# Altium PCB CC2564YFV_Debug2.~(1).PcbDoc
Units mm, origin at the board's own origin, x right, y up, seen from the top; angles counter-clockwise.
Board outline 229.87 x 45.72 mm, 2 copper layers (Top Layer, Bottom Layer); 77 components, 123 nets, 422 pads, 88 vias.
Unrouted connection lines stored in the file: 7.
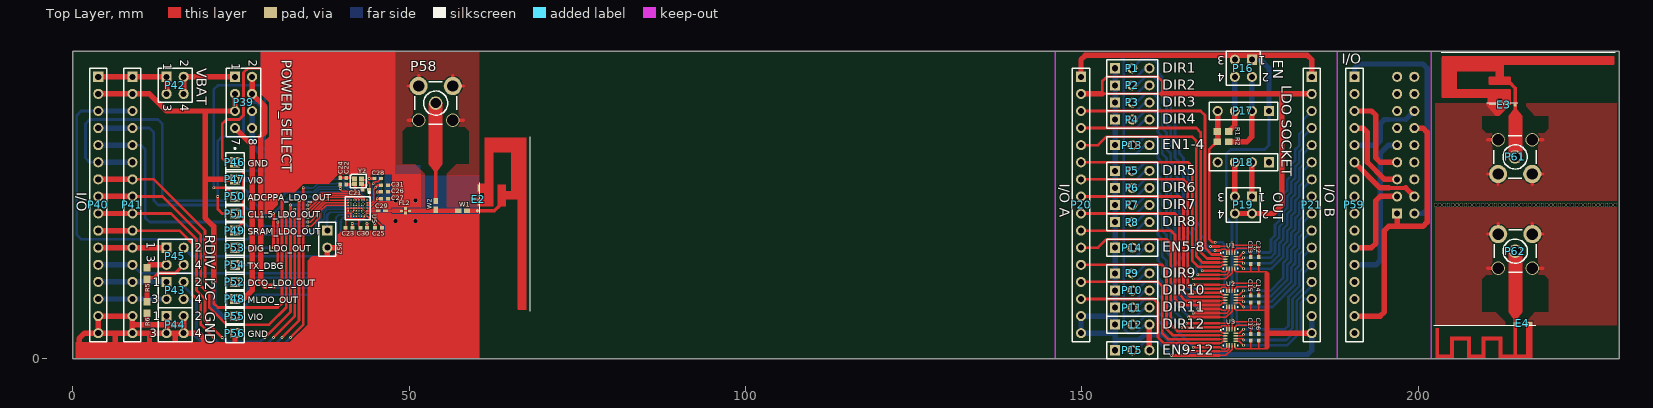
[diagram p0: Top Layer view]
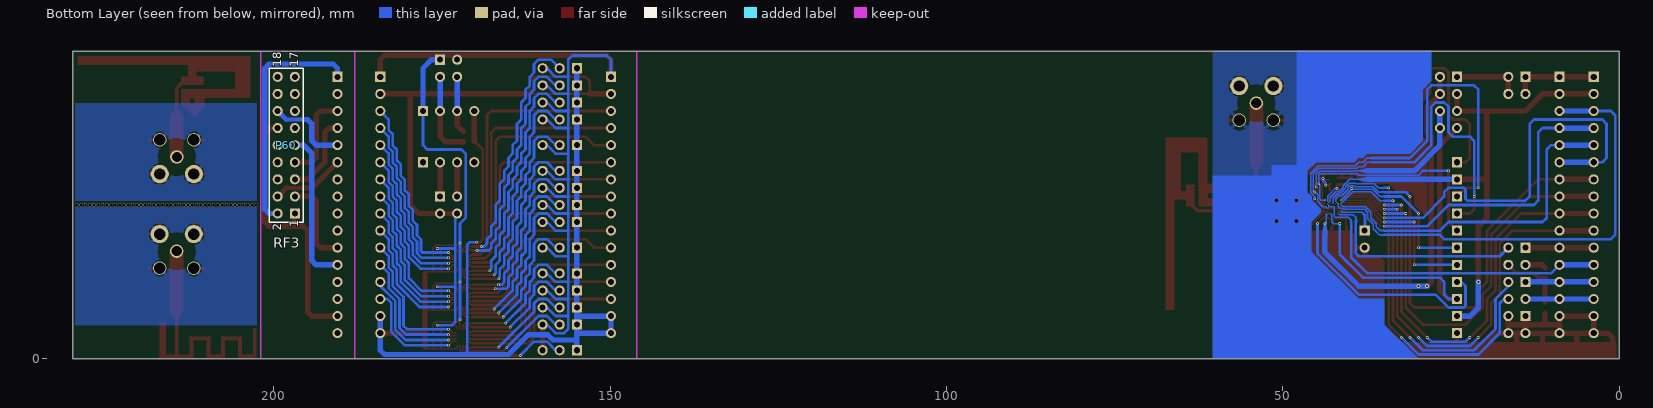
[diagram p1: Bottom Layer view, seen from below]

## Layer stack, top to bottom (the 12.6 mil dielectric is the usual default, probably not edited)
Top Solder: solder mask 0.0102, Solder Resist, Dk 3.5
Top Layer: signal copper 0.0356
Dielectric 1: dielectric 0.32, FR-4, Dk 4.8
Bottom Layer: signal copper 0.0356
Bottom Solder: solder mask 0.0102, Solder Resist, Dk 3.5

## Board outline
0,0 229.87,0 229.87,45.72 0,45.72

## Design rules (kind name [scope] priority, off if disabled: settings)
Clearance [All] p1: gap=0.1
ComponentClearance [All] p1 off: gap=0.1 collisioncheckmode=3 verticalgap=0.1 showdistances=FALSE
HoleSize [All] p1: absolutevalues=TRUE maxlimit=2.54 minlimit=0.1 maxpercent=80.000 minpercent=20.000
HoleToHoleClearance [All] p1: gap=0.1 allowstackedmicrovias=TRUE
MinimumSolderMaskSliver [All] p1: minsoldermaskwidth=0.1
PolygonConnect [All] p1: connectstyle=Relief reliefconductorwidth=0.5 reliefentries=4 polygonreliefangle="45 Angle" airgapwidth=0.2
RoutingVias [All] p1: holewidth=0.2 width=0.25 viastyle="Through Hole" minholewidth=0.1 minwidth=0.25 maxholewidth=0.2 maxwidth=0.45
SilkToSilkClearance [All] p1: silktosilkclearance=0.1
SilkToSolderMaskClearance [IsPad] p1 off: minsilkscreentomaskgap=0.1 clearancetoexposedcopper=TRUE
SolderMaskExpansion [All] p1: expansion=0.102
Width [All] p1: maxlimit=6 minlimit=0.1 preferedwidth=0.2
23 further rules are at their usual default settings.

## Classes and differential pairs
component class CC2564YFV_Debug_Add: E3 E4 P59 P60 P61 P62
component class CC2564YFV_Debug_Power: C12 C13 C14 C15 C16 C17 P1 P2 P3 P4 P5 P6 P7 P8 P9 P10 P11 P12 P13 P14 P15 P16 P17 P18 P19 P20 P21 R1 R2 U1 U2 U3
component class CC2564YFV_Debug_RF2: C21 C22 C23 C24 C25 C26 C27 C28 C29 C30 C31 E2 FL2 P39 P40 P41 P42 P43 P44 P45 P46 P47 P48 P49 P50 P51 P52 P53 P54 P55 P56 P57 P58 R5 R6 U5 W1 W2 Y2

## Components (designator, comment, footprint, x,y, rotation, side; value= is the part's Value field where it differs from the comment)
C12 "CC0402KRX7R8BB104" 0402 176.3,14.6 r270 top
C13 "CC0402KRX7R8BB104" 0402 175.1,14.6 r90 top
C14 "CC0402KRX7R8BB104" 0402 176.3,8.9 r270 top
C15 "CC0402KRX7R8BB104" 0402 175.1,8.9 r90 top
C16 "CC0402KRX7R8BB104" 0402 176.3,3.2 r270 top
C17 "CC0402KRX7R8BB104" 0402 175.1,3.2 r90 top
C21 "Cap Semi 8 pF" 0402 43.56,25.1 r0 top
C22 "Cap Semi 8 pF" 0402 40.66,26.4 r270 top
C23 "C1005X5R1A105K050BB" 0402 41.06,19.5 r0 top
C24 "C1005X7R1H104M050BB" 0402 39.76,26.4 r270 top
C25 "C1005X7R1H104M050BB" 0402 45.46,19.5 r180 top
C26 "C1005X7R1H104M050BB" 0402 46.36,24.8 r180 top
C27 "C1005X7R1H104M050BB" 0402 46.36,23.8 r180 top
C28 "C1005X7R1H104M050BB" 0402 45.36,26.8 r0 top
C29 "GRM0335C1E220JA01D" 1-0201 45.96,22 r0 top
C30 "C1005X7R1H104M050BB" 0402 43.26,19.5 r0 top
C31 "C1005X5R1A105K050BB" 0402 46.36,25.8 r180 top
E2 "Inverted F Antenna" Inverted_F_Antenna 60.16,22 r270 top
E3 "Inverted F Antenna" Inverted_F_Antenna 214.38,37.7 r0 top
E4 "Meandered IFA" Meandered_IFA 216.95,5 r180 top
FL2 "FI105L250014" FL105_Electrodes 49.46,22 r0 top
P1 "DIR1" HDR1X3 154.94,43.18 r0 top
P2 "DIR2" HDR1X3 154.94,40.64 r0 top
P3 "DIR3" HDR1X3 154.94,38.1 r0 top
P4 "DIR4" HDR1X3 154.94,35.56 r0 top
P5 "DIR5" HDR1X3 154.94,27.94 r0 top
P6 "DIR6" HDR1X3 154.94,25.4 r0 top
P7 "DIR7" HDR1X3 154.94,22.86 r0 top
P8 "DIR8" HDR1X3 154.94,20.32 r0 top
P9 "DIR9" HDR1X3 154.94,12.7 r0 top
P10 "DIR10" HDR1X3 154.94,10.16 r0 top
P11 "DIR11" HDR1X3 154.94,7.62 r0 top
P12 "DIR12" HDR1X3 154.94,5.08 r0 top
P13 "EN1-4" HDR1X3 154.94,31.75 r0 top
P14 "EN5-8" HDR1X3 154.94,16.51 r0 top
P15 "EN9-12" HDR1X3 154.94,1.27 r0 top
P16 "EN" HDR2X2 175.26,44.45 r180 top
P17 "LDO SOCKET" HDR1X4 177.8,36.83 r180 top
P18 "LDO SOCKET" HDR1X4 177.8,29.21 r180 top
P19 "OUT" HDR2X2 175.26,24.13 r180 top
P20 "I/O A" HDR1X16 149.86,41.91 r270 top
P21 "I/O B" HDR1X16 184.15,41.91 r270 top
P39 "POWER_SELECT" HDR2X4 24.13,41.91 r270 top
P40 "I/O" HDR1X16 3.81,41.91 r270 top
P41 "I/O" HDR1X16 8.89,41.91 r270 top
P42 "VBAT" HDR2X2 13.97,41.91 r270 top
P43 "I2C" HDR2X2 13.97,11.43 r270 top
P44 "GND" HDR2X2 13.97,6.35 r270 top
P45 "RDIV" HDR2X2 13.97,16.51 r270 top
P46 "GND" PIN1 24.13,29.21 r0 top
P47 "VIO" PIN1 24.13,26.67 r0 top
P48 "MLDO_OUT" PIN1 24.13,8.89 r0 top
P49 "SRAM_LDO_OUT" PIN1 24.13,19.05 r0 top
P50 "ADCPPA_LDO_OUT" PIN1 24.13,24.13 r0 top
P51 "CL1.5_LDO_OUT" PIN1 24.13,21.59 r0 top
P52 "DCO_LDO_OUT" PIN1 24.13,11.43 r0 top
P53 "DIG_LDO_OUT" PIN1 24.13,16.51 r0 top
P54 "TX_DBG" PIN1 24.13,13.97 r0 top
P55 "VIO" PIN1 24.13,6.35 r0 top
P56 "GND" PIN1 24.13,3.81 r0 top
P57 "G5" HDR1X2 37.846,19.05 r270 top
P58 "SMA" SMA#1 53.96,38 r0 top
P59 "I/O" HDR1X16 190.5,41.91 r270 top
P60 "RF3" HDR2X9 196.85,21.59 r90 bottom
P61 "SMA" SMA#2 214.38,30 r0 top
P62 "SMA" SMA#1 214.4,16 r0 top
R1 "Res Chip 10 K" 3-0603 170.942,33.782 r0 top
R2 "Res Chip 10 K" 3-0603 170.942,32.258 r0 top
R5 "Res Chip 10 K" 3-0603 11.049,12.7 r90 top
R6 "Res Chip 12 K" 3-0603 11.049,7.62 r90 top
U1 "SN74AVC4T774RSV" RSV16 172.1,14.6 r0 top
U2 "SN74AVC4T774RSV" RSV16 172.1,8.9 r0 top
U3 "SN74AVC4T774RSV" RSV16 172.1,3.2 r0 top
U5 "CC2564YFV" "YFV (R-XBGA-N54)" 42.36,22.2 r270 top
W1 "Chip Jumper Short" 2-0402 57.96,22 r180 top
W2 "Chip Jumper Open" 2-0402 53.96,22.8 r90 top
Y2 "NX1612AA-26MHZ-TI2" XTAL_QUAD_1.6x1.2mm 42.435,26.375 r180 top

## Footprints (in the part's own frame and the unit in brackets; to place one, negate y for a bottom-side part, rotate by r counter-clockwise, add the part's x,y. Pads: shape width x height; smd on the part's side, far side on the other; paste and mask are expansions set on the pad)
1-0201 [mm] "Chip Resistor; Body 0.6 x 0.3 mm (LxW typ)"
  rect 0.7x0.4 smd: 1(-0.525,0) 2(0.525,0)
2-0402 [mm] "Chip Resistor; Body 1 x 0.5 mm (LxW typ)"
  rect 0.9x0.7 smd: 1(-0.65,0) 2(0.65,0)
3-0603 [mm] "Chip Resistor; Body 1.6 x 0.9 mm (LxW typ)"
  rect 1.1x1 smd: 1(-0.85,0) 2(0.85,0)
0402 [mm] "Chip Capacitor, Body 1.0x0.5mm, IPC High Density"
  rect 0.6x0.5 smd: 1(-0.5,0) 2(0.5,0)
  body extent -0.55,-0.3 0.55,0.3, height 1.3
FL105_Electrodes [mm]
  round 0.6 hole 0.6: 1(-1.5,1.5) 1(1.5,1.5) 3(-1.5,-1.5) 3(1.5,-1.5)
  rect 0.4x0.45 smd: 1(0,0.35) 3(0,-0.35)
  rect 0.45x0.3 smd: 2(0.575,0) 4(-0.575,0)
  Top Layer region: -2,0.5 2,0.5 2,2 -2,2
  Top Layer region: -2,-2 2,-2 2,-0.5 -2,-0.5
  Top Layer region: -2,-0.3 -0.5,-0.3 -0.5,0.3 -2,0.3
  Top Layer region: 0.5,-0.3 2,-0.3 2,0.3 0.5,0.3
  Top Layer region: -0.2,-0.5 0.2,-0.5 0.2,0.5 -0.2,0.5
  Top Layer region: 0.425,-0.15 0.5,-0.3 0.5,-0.15
  Top Layer region: -0.425,-0.15 -0.5,-0.3 -0.5,-0.15
  Top Layer region: 0.425,0.15 0.5,0.3 0.5,0.15
  Top Layer region: -0.5,0.3 -0.425,0.15 -0.5,0.15
HDR1X2 [mm] "Connector; Header; 2 Position"
  rect 1.5x1.5 hole 0.9: 1(0,0)
  round 1.5 hole 0.9: 2(2.54,0)
  silkscreen extent -1.27,-1.27 3.81,1.27
HDR1X3 [mm] "Connector; Header; 3 Position"
  rect 1.5x1.5 hole 0.9: 1(0,0)
  round 1.5 hole 0.9: 2(2.54,0) 3(5.08,0)
  silkscreen extent -1.27,-1.27 6.35,1.27
HDR1X4 [mm] "Connector; Header; 4 Position"
  rect 1.5x1.5 hole 0.9: 1(0,0)
  round 1.5 hole 0.9: 2(2.54,0) 3(5.08,0) 4(7.62,0)
  silkscreen extent -1.27,-1.27 8.89,1.27
HDR1X16 [mm] "Connector; Header; 16 Position"
  rect 1.5x1.5 hole 0.9: 1(0,0)
  round 1.5 hole 0.9: 2(2.54,0) 3(5.08,0) 4(7.62,0) 5(10.16,0) 6(12.7,0) 7(15.24,0) 8(17.78,0) 9(20.32,0) 10(22.86,0) 11(25.4,0) 12(27.94,0) 13(30.48,0) 14(33.02,0) 15(35.56,0) 16(38.1,0)
  silkscreen extent -1.27,-1.27 39.37,1.27
HDR2X2 [mm] "Connector; Header; 2x2 Position"
  rect 1.5x1.5 hole 0.9: 1(0,0)
  round 1.5 hole 0.9: 2(0,2.54) 3(2.54,0) 4(2.54,2.54)
  silkscreen extent -1.27,-1.27 3.81,3.81
HDR2X4 [mm] "Connector; Header; 4x2 Position"
  rect 1.5x1.5 hole 0.9: 1(0,0)
  round 1.5 hole 0.9: 2(0,2.54) 3(2.54,0) 4(2.54,2.54) 5(5.08,0) 6(5.08,2.54) 7(7.62,0) 8(7.62,2.54)
  silkscreen extent -1.27,-1.27 8.89,3.81
HDR2X9 [mm] "Connector; Header; 9x2 Position"
  rect 1.5x1.5 hole 0.9: 1(0,0)
  round 1.5 hole 0.9: 2(0,2.54) 3(2.54,0) 4(2.54,2.54) 5(5.08,0) 6(5.08,2.54) 7(7.62,0) 8(7.62,2.54) 9(10.16,0) 10(10.16,2.54) 11(12.7,0) 12(12.7,2.54) 13(15.24,0) 14(15.24,2.54) 15(17.78,0) 16(17.78,2.54) 17(20.32,0) 18(20.32,2.54)
  silkscreen extent -1.27,-1.27 21.59,3.81
Inverted_F_Antenna [mm]
  round 0.46 smd mask+0: 1(0,0)
  rect 1x0.3 smd paste+0 mask+0: 2(-1.272,0.165) 3(-3.367,0.183)
  Top Layer region: -10.77,1.092 -10.237,1.092 -4.039,1.067 -4.039,0.127 -4.032,0.088 -4.009,0.055 -3.976,0.033 -3.937,0.025 -3.937,0.025 -2.788,0.025 -2.749,0.033 -2.716,0.055 -2.694,0.088 -2.686,0.127 -2.686,0.127 -2.686,1.025 -1.89,1.025 -1.89,0.127 -1.882,0.088 -1.86,0.055 -1.827,0.033 -1.788,0.025 -1.788,0.025 -0.788,0.025 -0.767,0.027 -0.747,0.033 -0.747,0.033 -0.702,0.051 -0.669,0.087 -0.658,0.135 -0.658,0.135 -0.658,0.135 -0.658,0.135 -0.658,0.135 -0.66,2.23 -0.67,2.274 -0.698,2.309 -0.698,2.309 -0.698,2.309 -0.721,2.338 -0.752,2.356 -0.788,2.363 -0.788,2.363 -8.686,2.363 -8.686,5.025 -2.89,5.025 -2.89,4.229 -3.788,4.229 -3.827,4.221 -3.86,4.199 -3.882,4.166 -3.89,4.127 -3.89,4.127 -3.89,3.127 -3.882,3.088 -3.86,3.055 -3.827,3.033 -3.788,3.025 -3.788,3.025 -0.83,3.025 -0.231,2.426 -0.231,0 -0.208,-0.1 -0.144,-0.18 -0.052,-0.225 0.051,-0.225 0.143,-0.18 0.207,-0.1 0.23,0 0.23,0 0.23,2.521 0.212,2.61 0.162,2.685 0.162,2.685 -0.686,3.533 -0.686,4.127 -0.694,4.166 -0.716,4.199 -0.749,4.221 -0.788,4.229 -0.788,4.229 -1.686,4.229 -1.686,6.025 14.63,6.025 14.669,6.033 14.702,6.055 14.724,6.088 14.732,6.127 14.732,6.127 14.732,7.137 14.724,7.176 14.702,7.21 14.669,7.232 14.63,7.239 14.63,7.239 -10.77,7.239 -10.809,7.232 -10.842,7.21 -10.864,7.176 -10.872,7.137 -10.872,7.137 -10.872,1.194 -10.864,1.155 -10.842,1.122 -10.809,1.1 -10.77,1.092
  silkscreen extent -11,0.34 14.9,7.86
Meandered_IFA [mm] "Meandered Inverted F Antenna"
  rect 0.5x0.5 smd mask+0: 1(2.55,-0.25)
  rect 0.9x0.5 smd mask+0: 2(0.45,-0.25)
  Top Layer region: 0,-0.5 0,4.89 5,4.89 5,2.25 7,2.25 7,4.89 9.7,4.89 9.7,2.25 11.7,2.25 11.7,4.89 14.4,4.89 14.4,0.45 13.9,0.45 13.9,4.39 12.2,4.39 12.2,1.75 9.2,1.75 9.2,4.39 7.5,4.39 7.5,1.75 4.5,1.75 4.5,4.39 2.8,4.39 2.8,-0.5 2.3,-0.5 2.3,4.39 0.9,4.39 0.9,-0.5
  silkscreen extent -0.5,0 14.7,0
PIN1 [mm] "Connector; Plug"
  rect 1.5x1.5 hole 0.9: 1(0,0)
  silkscreen extent -1.4,-1.4 1.4,2.17
RSV16 [mm] "QFN, 16-Leads, Body 1.8x2.6mm, Pitch 0.4mm, TI Recommended"
  rect 0.75x0.2 smd paste-0.1 mask+0.05: 1(-0.725,0.6)
  rect 0.65x0.2 smd paste-0.1 mask+0.05: 2(-0.775,0.2) 3(-0.775,-0.2) 4(-0.775,-0.6) 9(0.775,-0.6) 10(0.775,-0.2) 11(0.775,0.2) 12(0.775,0.6)
  rect 0.2x0.65 smd paste-0.1 mask+0.05: 5(-0.6,-1.175) 6(-0.2,-1.175) 7(0.2,-1.175) 8(0.6,-1.175) 13(0.6,1.175) 14(0.2,1.175) 15(-0.2,1.175) 16(-0.6,1.175)
  silkscreen extent -1.52,-1.33 1.08,1.33, body extent -0.92,-1.32 0.92,1.33, height 0.55
SMA#1 [mm] "Connector; SMA Generic"
  round 2 hole 1.5: 1(0,0)
  round 2 hole 1.7: 2(-2.54,-2.54) 2(2.54,-2.54)
  round 2.7 hole 1.7: 2(-2.54,2.54) 2(2.54,2.54)
  silkscreen extent -3.15,-3.15 3.15,3.15
SMA#2 [mm] "Connector; SMA Generic"
  round 2 hole 1.5: 1(0,0)
  round 2.7 hole 1.7: 2(-2.54,-2.54) 2(2.54,-2.54)
  round 2 hole 1.7: 2(-2.54,2.54) 2(2.54,2.54)
  silkscreen extent -3.15,-3.15 3.15,3.15
XTAL_QUAD_1.6x1.2mm [mm]
  rect 0.75x0.65 smd: 1(-0.525,-0.375) 2(0.525,-0.375) 3(0.525,0.375) 4(-0.525,0.375)
  silkscreen extent -1.2,-1.02 1.2,0.98
"YFV (R-XBGA-N54)" [mm] "BGA, 54-Balls, Pitch 0.4mm"
  round 0.2 smd: A1(-1.4,1.4) A2(-1,1.4) A3(-0.6,1.4) A4(-0.2,1.4) A5(0.2,1.4) A6(0.6,1.4) A7(1,1.4) B1(-1.4,1) B2(-1,1) B3(-0.6,1) B4(-0.2,1) B6(0.6,1) B7(1,1) C1(-1.4,0.6) C2(-1,0.6) C3(-0.6,0.6) C4(-0.2,0.6) C5(0.2,0.6) C6(0.6,0.6) C7(1,0.6) D1(-1.4,0.2) D2(-1,0.2) D3(-0.6,0.2) D4(-0.2,0.2) D5(0.2,0.2) D6(0.6,0.2) D7(1,0.2) E1(-1.4,-0.2) E2(-1,-0.2) E3(-0.6,-0.2) E4(-0.2,-0.2) E5(0.2,-0.2) E6(0.6,-0.2) E7(1,-0.2) F1(-1.4,-0.6) F2(-1,-0.6) F3(-0.6,-0.6) F4(-0.2,-0.6) F5(0.2,-0.6) F6(0.6,-0.6) F7(1,-0.6) G1(-1.4,-1) G2(-1,-1) G3(-0.6,-1) G4(-0.2,-1) G5(0.2,-1) G6(0.6,-1) G7(1,-1) H1(-1.4,-1.4) H2(-1,-1.4) H3(-0.6,-1.4) H4(-0.2,-1.4) H5(0.2,-1.4) H7(1,-1.4)
  silkscreen extent -2.65,-1.88 1.52,1.88, body extent -1.91,-1.91 1.52,1.91, height 0.5

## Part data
C12 C13 C14 C15 C16 C17: "0.1 uF/25 V 0402"
C21 C22: "Chip Capacitor, 8 pF"
C23 C31: "1.0 uF/10 V 0402"
C24 C25 C26 C27 C28 C30: "0.1 uF/50 V 0402"
C29: "22 pF/25 V 0201"
E2 E3: "Inverted F Antenna (Design Note DN0007; SWRU120B)"
E4: "Meandered Inverted F Antenna (Application Note AN043; SWRA117D)"
FL2: "2.4 GHz Low Pass Filter"
P1 P2 P3 P4 P5 P6 P7 P8 P9 P10 P11 P12 P13 P14 P15: library part "Header 3", "Header, 3-Pin"
P16 P19 P42 P43 P44 P45: library part "Header 2X2", "Header, 2-Pin, Dual row"
P17 P18: library part "Header 4", "Header, 4-Pin"
P20 P21 P40 P41 P59: library part "Header 16", "Header, 16-Pin"
P39: library part "Header 4X2", "Header, 4-Pin, Dual row"
P46 P47 P48 P49 P50 P51 P52 P53 P54 P55 P56: library part Plug, "Plug"
P57: library part "Header 2", "Header, 2-Pin"
P58 P61 P62: "SMA Generic Connector"
P60: library part "Header 9X2", "Header, 9-Pin, Dual row"
R1 R2 R5: "Chip Resistor, 10 K"
R6: "Chip Resistor, 12 K"
U1 U2 U3: "4-Bit Dual-Supply Bus Transceiver With Configurable Voltage Translation and 3-State Outputs"
U5: "CC2564, 54-balls DSBGA"
Y2: "Crystal Oscillator 26 MHz"

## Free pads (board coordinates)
  round 0.5 hole 0.5 paste+0 mask+0: 0(202.565,22.86) 0(203.2,22.86) 0(203.835,22.86) 0(204.47,22.86) 0(205.105,22.86) 0(205.74,22.86) 0(206.375,22.86) 0(207.01,22.86) 0(207.645,22.86) 0(208.28,22.86) 0(208.915,22.86) 0(209.55,22.86) 0(210.185,22.86) 0(210.82,22.86) 0(211.455,22.86) 0(212.09,22.86) 0(212.725,22.86) 0(213.36,22.86) 0(213.995,22.86) 0(214.63,22.86) 0(215.265,22.86) 0(215.9,22.86) 0(216.535,22.86) 0(217.17,22.86) 0(217.805,22.86) 0(218.44,22.86) 0(219.075,22.86) 0(219.71,22.86) 0(220.345,22.86) 0(220.98,22.86) 0(221.615,22.86) 0(222.25,22.86) 0(222.885,22.86) 0(223.52,22.86) 0(224.155,22.86) 0(224.79,22.86) 0(225.425,22.86) 0(226.06,22.86) 0(226.695,22.86) 0(227.33,22.86) 0(227.965,22.86) 0(228.6,22.86) 0(229.235,22.86)

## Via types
v1: diameter 0.4, hole 0.2, Top Layer to Bottom Layer, 70 vias
v2: diameter 0.25, hole 0.1, Top Layer to Bottom Layer, 15 vias
v3: diameter 0.6, hole 0.3, Top Layer to Bottom Layer, 3 vias

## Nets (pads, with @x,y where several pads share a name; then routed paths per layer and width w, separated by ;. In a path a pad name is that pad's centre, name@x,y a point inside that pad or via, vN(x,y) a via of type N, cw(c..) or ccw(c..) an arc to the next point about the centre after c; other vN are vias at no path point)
A1: P20.3 U1.1 | length 42
  Top Layer w0.2: 170.4,15.5 170.6,15.5 170.9,15.2 U1.1
  Top Layer w0.4: P20.3 167.64,36.83 168.275,36.195 168.275,16.51 169.285,15.5 170.4,15.5
A2: P20.4 U1.2 | length 40
  Top Layer w0.2: 170.4,14.9 170.8,14.9 170.9,14.8 U1.2
  Top Layer w0.4: P20.4 167.005,34.29 167.64,33.655 167.64,15.875 168.615,14.9 170.4,14.9
A3: P20.5 U1.3 | length 39.8
  Top Layer w0.2: 170.4,14.3 170.8,14.3 170.9,14.4 U1.3
  Top Layer w0.4: P20.5 152.4,31.75 153.67,33.02 166.37,33.02 167.005,32.385 167.005,15.24 167.945,14.3 170.4,14.3
A4: P20.6 U1.4 | length 36.2
  Top Layer w0.2: 170.4,13.7 170.6,13.7 170.9,14 U1.4
  Top Layer w0.4: P20.6 165.735,29.21 166.37,28.575 166.37,14.605 167.275,13.7 170.4,13.7
A5: P20.7 U2.1 | length 37.6
  Top Layer w0.2: 170.4,9.8 170.6,9.8 170.9,9.5 U2.1
  Top Layer w0.4: P20.7 165.1,26.67 165.735,26.035 165.735,10.795 166.73,9.8 170.4,9.8
A6: P20.8 U2.2 | length 35.5
  Top Layer w0.2: 170.4,9.2 170.8,9.2 170.9,9.1 U2.2
  Top Layer w0.4: P20.8 164.465,24.13 165.1,23.495 165.1,10.16 166.06,9.2 170.4,9.2
A7: P20.9 U2.3 | length 33.6
  Top Layer w0.2: 170.4,8.6 170.8,8.6 170.9,8.7 U2.3
  Top Layer w0.4: P20.9 163.83,21.59 164.465,20.955 164.465,9.525 165.39,8.6 170.4,8.6
A8: P20.10 U2.4 | length 31.7
  Top Layer w0.2: 170.4,8 170.6,8 170.9,8.3 U2.4
  Top Layer w0.4: P20.10 163.195,19.05 163.83,18.415 163.83,8.89 164.72,8 170.4,8
A9: P20.11 U3.1 | length 34.9
  Top Layer w0.2: 170.4,4.1 170.6,4.1 170.9,3.8 U3.1
  Top Layer w0.4: P20.11 152.4,16.51 153.67,17.78 162.56,17.78 163.195,17.145 163.195,5.08 164.175,4.1 170.4,4.1
A10: P20.12 U3.2 | length 31.1
  Top Layer w0.2: 170.4,3.5 170.8,3.5 170.9,3.4 U3.2
  Top Layer w0.4: P20.12 161.925,13.97 162.56,13.335 162.56,4.445 163.505,3.5 170.4,3.5
A11: P20.13 U3.3 | length 29.1
  Top Layer w0.2: 170.4,2.9 170.8,2.9 170.9,3 U3.3
  Top Layer w0.4: P20.13 161.29,11.43 161.925,10.795 161.925,3.81 162.835,2.9 170.4,2.9
A12: P20.14 U3.4 | length 27.3
  Top Layer w0.2: 170.4,2.3 170.6,2.3 170.9,2.6 U3.4
  Top Layer w0.4: P20.14 160.655,8.89 161.29,8.255 161.29,3.175 162.165,2.3 170.4,2.3
ADCPPA_LDO_OUT_1: 
ADCPPA_LDO_OUT_2: C27.2 P50.1 U5.A4 | length 60
  Top Layer w0.2: U5.A4 44.06,22.4 v1@45.26,23.6
  Top Layer w0.4: v1(20.955,25.4) 22.86,25.4 P50.1 ; v1(45.26,23.8) C27.2
  Bottom Layer w0.2: 36.83,29.845 37.465,29.845 38.1,29.21 38.735,29.21 39.245,28.7 44.76,28.7 45.86,27.6 45.86,24.7 45.26,24.1 v1(45.26,23.8)
  Bottom Layer w0.4: v1(20.955,25.4) 20.955,40.005 21.59,40.64 27.94,40.64 28.575,40.005 28.575,32.385 31.115,29.845 36.83,29.845
ANTENNA: FL2.2 W1.2 W2.1 | length 6.8
  Top Layer w0.6: 50.46,22 W1.2
AUD_CLK_2: P40.8 P41.8 U5.E1 | length 68
  Top Layer w0.2: v1(34.925,21.59) 34.95,21.59 37.36,24 41.784,24 42.16,23.624 U5.E1
  Top Layer w0.4: P41.8 13.335,24.13 19.05,18.415 19.05,10.795 20.32,9.525 20.32,7.62 22.86,5.08 29.21,5.08 31.75,7.62 v1(31.75,21.59)
  Top Layer w0.8: P40.8 P41.8
  Bottom Layer w0.4: v1(31.75,21.59) v1(34.925,21.59)
AUD_FSYNC_2: P40.7 P41.7 U5.E2 | length 70.2
  Top Layer w0.4: P41.7 12.065,26.67 19.685,19.05 19.685,11.43 20.955,10.16 20.955,8.255 21.59,7.62 30.48,7.62 31.115,8.255 v1(31.115,24.13)
  Top Layer w0.8: P40.7 P41.7
  Bottom Layer w0.2: 34.925,24.765 35.725,24.765 36.56,25.6 39.36,25.6 39.46,25.7 40.06,25.7 40.26,25.5 40.26,25.2 41.26,24.2 41.76,24.2 42.16,23.8 v2(42.16,23.2)
  Bottom Layer w0.4: v1(31.115,24.13) 31.75,24.765 34.925,24.765
AUD_IN_2: P40.9 P41.9 U5.C1 | length 72.3
  Top Layer w0.2: v1(34.925,22.86) 35.22,22.86 36.96,24.6 42.136,24.6 42.96,23.776 U5.C1
  Top Layer w0.4: P41.9 14.605,21.59 18.415,17.78 18.415,10.16 19.685,8.89 19.685,5.715 v1(22.225,3.175) ; v1(28.575,3.175) 32.385,6.985 v1(32.385,22.86)
  Top Layer w0.8: P40.9 P41.9
  Bottom Layer w0.4: v1(22.225,3.175) 22.86,2.54 27.94,2.54 v1(28.575,3.175) ; v1(32.385,22.86) v1(34.925,22.86)
AUD_OUT_2: P40.10 P41.10 U5.D1 | length 71.1
  Top Layer w0.2: v1(34.925,22.225) 35.085,22.225 37.16,24.3 41.96,24.3 42.56,23.7 U5.D1
  Top Layer w0.4: P41.10 15.875,19.05 17.78,17.145 17.78,9.525 19.05,8.255 19.05,5.08 v1(20.955,3.175) ; v1(29.845,3.175) 33.02,6.35 v1(33.02,22.225)
  Top Layer w0.8: P40.10 P41.10
  Bottom Layer w0.4: v1(20.955,3.175) 22.225,1.905 28.575,1.905 v1(29.845,3.175) ; v1(33.02,22.225) v1(34.925,22.225)
B1: P21.3 U1.12 | length 28.9
  Top Layer w0.2: U1.12 173.4,15.2 v1(174,15.8)
  Bottom Layer w0.4: v1(174,15.8) 177.9,15.8 178.1,16 178.1,17.7 178.7,18.3 178.7,19.9 179.3,20.5 179.3,22.1 179.9,22.7 179.9,24.4 180.5,25 180.5,26.6 181.1,27.2 181.1,28.9 181.7,29.5 181.7,31.1 182.3,31.7 182.3,33.4 182.9,34 182.9,35.58 P21.3
B2: P21.4 U1.11 | length 27
  Top Layer w0.2: U1.11 173.8,14.8 v1(174,15)
  Bottom Layer w0.4: v1(174,15) 178,15 178.7,15.7 178.7,17.4 179.3,18 179.3,19.6 179.9,20.2 179.9,21.8 180.5,22.4 180.5,24.1 181.1,24.7 181.1,26.3 181.7,26.9 181.7,28.6 182.3,29.2 182.3,30.8 182.9,31.4 182.9,33.04 P21.4
B3: P21.5 U1.10 | length 25.4
  Top Layer w0.2: U1.10 173.8,14.4 v1(174,14.2)
  Bottom Layer w0.4: v1(174,14.2) 178.1,14.2 179.3,15.4 179.3,17.1 179.9,17.7 179.9,19.3 180.5,19.9 180.5,21.5 181.1,22.1 181.1,23.8 181.7,24.4 181.7,26 182.3,26.6 182.3,28.3 182.9,28.9 182.9,30.5 P21.5
B4: P21.6 U1.9 | length 23.8
  Top Layer w0.2: U1.9 173.4,14 v1(174,13.4)
  Bottom Layer w0.4: v1(174,13.4) 178.2,13.4 179.9,15.1 179.9,16.8 180.5,17.4 180.5,19 181.1,19.6 181.1,21.2 181.7,21.8 181.7,23.5 182.3,24.1 182.3,25.7 182.9,26.3 182.9,27.96 P21.6
B5: P21.7 U2.12 | length 24.5
  Top Layer w0.2: U2.12 173.4,9.5 v1(174,10.1)
  Bottom Layer w0.4: v1(174,10.1) 178,10.1 179.9,12 179.9,14.2 180.5,14.8 180.5,16.5 181.1,17.1 181.1,18.7 181.7,19.3 181.7,20.9 182.3,21.5 182.3,23.2 182.9,23.8 182.9,25.42 P21.7
B6: P21.8 U2.11 | length 22.6
  Top Layer w0.2: U2.11 173.8,9.1 v1(174,9.3)
  Bottom Layer w0.4: v1(174,9.3) 178.1,9.3 180.5,11.7 180.5,13.9 181.1,14.5 181.1,16.2 181.7,16.8 181.7,18.4 182.3,19 182.3,20.6 182.9,21.2 182.9,22.88 P21.8
B7: P21.9 U2.10 | length 21
  Top Layer w0.2: U2.10 173.8,8.7 v1(174,8.5)
  Bottom Layer w0.4: v1(174,8.5) 178.2,8.5 181.1,11.4 181.1,13.6 181.7,14.2 181.7,15.9 182.3,16.5 182.3,18.1 182.9,18.7 182.9,20.34 P21.9
B8: P21.10 U2.9 | length 19.4
  Top Layer w0.2: U2.9 173.4,8.3 v1(174,7.7)
  Bottom Layer w0.4: v1(174,7.7) 178.3,7.7 181.7,11.1 181.7,13.3 182.3,13.9 182.3,15.6 182.9,16.2 182.9,17.8 P21.10
B9: P21.11 U3.12 | length 21.3
  Top Layer w0.2: U3.12 173.4,3.8 v1(174,4.4)
  Bottom Layer w0.4: v1(174,4.4) 180.2,4.4 180.7,4.9 180.7,9.2 182.3,10.8 182.3,13 182.9,13.6 182.9,15.26 P21.11
B10: P21.12 U3.11 | length 19.5
  Top Layer w0.2: U3.11 173.8,3.4 v1(174,3.6)
  Bottom Layer w0.4: v1(174,3.6) 180.3,3.6 181.3,4.6 181.3,8.9 182.9,10.5 182.9,12.72 P21.12
B11: P21.13 U3.10 | length 17.8
  Top Layer w0.2: U3.10 173.8,3 v1(174,2.8)
  Bottom Layer w0.4: v1(174,2.8) 180.4,2.8 181.9,4.3 181.9,8.6 184.15,10.85 P21.13
B12: P21.14 U3.9 | length 16.9
  Top Layer w0.2: U3.9 173.4,2.6 v1(174,2)
  Bottom Layer w0.4: v1(174,2) 180.5,2 182.5,4 182.5,8.3 183.09,8.89 P21.14
BT_CTS_1: 
BT_CTS_2: P40.6 P41.6 U5.H1 | length 68.1
  Top Layer w0.2: v1(34.925,20.955) 35.215,20.955 35.96,21.7 35.96,22.1 37.46,23.6 U5.H1
  Bottom Layer w0.4: P40.6 2.54,29.21 1.905,29.845 1.905,34.925 2.54,35.56 12.7,35.56 13.335,34.925 13.335,24.13 13.97,23.495 22.606,23.495 22.86,23.749 22.86,25.146 23.114,25.4 25.4,25.4 26.035,24.765 26.035,24.13 29.21,20.955 v1(34.925,20.955)
  Bottom Layer w0.8: P40.6 P41.6
BT_CTS_3: P59.6 P60.4 | length 11
  Top Layer w0.6: 195.58,25.4 198.12,25.4
  Top Layer w0.8: P59.6 194.31,25.4 195.58,25.4 ; 198.12,25.4 P60.4
BT_RTS_1: 
BT_RTS_2: P40.5 P41.5 U5.G3 | length 51.1
  Bottom Layer w0.2: 34.925,19.05 35.56,19.05 36.16,19.65 36.16,20.1 36.96,20.9 36.96,21.8 37.76,22.6 40.96,22.6 41.06,22.7 41.26,22.7 v2(41.36,22.8)
  Bottom Layer w0.4: P41.5 10.16,31.75 10.795,31.115 10.795,20.955 11.43,20.32 25.4,20.32 26.67,19.05 34.925,19.05
  Bottom Layer w0.8: P40.5 P41.5
BT_RTS_3: P59.5 P60.14 | length 12.5
  Bottom Layer w0.6: 195.58,35.56 198.12,35.56
  Bottom Layer w0.8: P59.5 193.675,31.75 194.31,32.385 194.31,34.925 194.945,35.56 195.58,35.56 ; 198.12,35.56 P60.14
BT_RX_1: 
BT_RX_2: P40.4 P41.4 U5.H3 | length 50.8
  Top Layer w0.2: v1@35.06,19.7 35.46,19.7 36.76,21 36.76,21.9 37.66,22.8 U5.H3
  Bottom Layer w0.4: P41.4 11.43,34.29 12.065,33.655 12.065,23.495 12.7,22.86 25.4,22.86 28.575,19.685 v1(34.925,19.685)
  Bottom Layer w0.8: P40.4 P41.4
BT_RX_3: P59.4 P60.5 | length 12.1
  Top Layer w0.8: P59.4 191.77,34.29 192.405,33.655 192.405,29.21 194.945,26.67 P60.5
BT_SHUTD_1: 
BT_SHUTD_2: P40.12 P41.12 U5.B3 | length 48.3
  Bottom Layer w0.2: 39.86,20.3 39.86,20.6 40.26,21 42.26,21 42.36,21.1 42.36,22.5 42.46,22.6 43.1,22.6 43.3,22.8 v2(43.36,22.8)
  Bottom Layer w0.4: P41.12 10.16,12.7 37.465,12.7 39.86,15.095 39.86,20.3
  Bottom Layer w0.8: P40.12 P41.12
BT_SHUTD_3: P59.12 P60.9 | length 23
  Bottom Layer w0.8: P59.12 193.675,13.97 194.31,14.605 194.31,30.48 195.58,31.75 P60.9
BT_TX_1: 
BT_TX_2: P40.3 P41.3 U5.F2 | length 70.6
  Bottom Layer w0.2: 34.925,18.415 35.675,18.415 36.56,19.3 36.56,20 37.36,20.8 37.36,21.7 37.86,22.2 41.06,22.2 41.26,22.4 41.56,22.4 41.76,22.6 v2(41.76,23.2)
  Bottom Layer w0.4: P40.3@3.175,36.83 1.27,36.83 0.635,36.195 0.635,18.415 1.27,17.78 26.035,17.78 26.67,18.415 34.925,18.415
  Bottom Layer w0.8: P40.3 P41.3
BT_TX_3: P59.3 P60.7 | length 13.2
  Top Layer w0.8: P59.3 193.04,36.83 193.675,36.195 193.675,29.845 194.31,29.21 P60.7
CL1.5_LDO_IN_1: 
CL1.5_LDO_IN_2: C30.2 P39.2 P39.4 U5.B6 | length 57.5
  Top Layer w0.4: C30.2 v1(43.76,20.1)
  Top Layer w0.8: P39.2 P39.4 28.575,37.465 28.575,33.655 27.94,33.02 27.94,11.43 v3(28.575,10.795) v3(29.845,10.795)
  Bottom Layer w0.2: v2(43.36,21.6) 43.56,21.4 43.56,20.3 v1(43.76,20.1)
  Bottom Layer w0.4: 43.76,18.5 v1(43.76,20.1)
  Bottom Layer w0.8: v3(28.575,10.795) 38.735,10.795 43.76,15.82 43.76,18.5
CL1.5_LDO_OUT_1: 
CL1.5_LDO_OUT_2: C26.2 P51.1 U5.B4 | length 56
  Top Layer w0.4: v1(21.59,24.13) 21.59,22.225 22.225,21.59 P51.1 ; v1(45.26,24.8) C26.2
  Bottom Layer w0.2: 36.83,29.21 37.465,29.21 38.1,28.575 38.735,28.575 39.01,28.3 44.66,28.3 45.46,27.5 45.46,25 v1(45.26,24.8) 44.86,24.4 44.86,23.4 44.06,22.6 43.66,22.6 43.46,22.4 v2(43.36,22.4)
  Bottom Layer w0.4: v1(21.59,24.13) 21.59,32.385 22.225,33.02 24.765,33.02 25.4,33.655 25.4,37.465 26.035,38.1 27.305,38.1 27.94,37.465 27.94,31.75 30.48,29.21 36.83,29.21
DCO_LDO_OUT_1: 
DCO_LDO_OUT_2: C25.2 P52.1 U5.A7 | length 36.4
  Top Layer w0.2: U5.A7 v1@44.96,20
  Top Layer w0.4: C25.2@44.96,19.6 v1@44.96,20
  Bottom Layer w0.4: P52.1 23.495,11.43 22.86,10.795 22.86,7.874 23.114,7.62 25.4,7.62 27.305,9.525 38.735,9.525 44.86,15.65 v1(44.86,20.1)
DIG_LDO_OUT_1: 
DIG_LDO_OUT_2: C24.2 P53.1 U5.B1 U5.G1 | length 29.6
  Top Layer w0.2: v1@39.76,25.2 40.06,24.9 42.26,24.9 43.36,23.8 U5.B1
  Top Layer w0.4: v1(29.845,16.51) v1(29.845,21.59) ; v1(39.76,25.3) C24.2 C24.2@39.76,26
  Bottom Layer w0.2: 34.925,24.13 35.56,24.13 ; 35.59,24.13 36.66,25.2 v1@39.76,25.2 ; v1(39.76,25.3) v1@39.76,25.2 ; v2(41.36,23.6) v1@39.76,25.2
  Bottom Layer w0.4: P53.1 v1(29.845,16.51) ; v1(29.845,21.59) 32.385,24.13 34.925,24.13
DIR1: P1.2 U1.15 | length 38.7
  Top Layer w0.2: 170.4,16.7 171.5,16.7 171.9,16.3 U1.15
  Top Layer w0.4: v1(169.1,16.7) 170.4,16.7
  Bottom Layer w0.4: P1.2 158.75,44.45 160.655,44.45 161.29,43.815 161.29,42.545 161.925,41.91 161.925,40.64 162.56,40.005 162.56,38.735 163.195,38.1 163.195,35.56 163.83,34.925 163.83,32.385 164.465,31.75 164.465,30.48 165.1,29.845 165.1,28.575 165.735,27.94 165.735,26.67 166.37,26.035 166.37,23.495 167.005,22.86 167.005,20.32 167.64,19.685 167.64,18.415 168.275,17.78 168.275,17.145 168.72,16.7 v1(169.1,16.7)
DIR2: P2.2 U1.16 | length 36.6
  Top Layer w0.2: 170.4,16.1 170.6,16.1 170.8,16.3 171.4,16.3 171.5,16.2 U1.16
  Top Layer w0.4: v1(169.77,16.1) 170.4,16.1
  Bottom Layer w0.4: P2.2 158.115,40.64 159.385,41.91 160.655,41.91 161.29,41.275 161.29,40.005 161.925,39.37 161.925,38.1 162.56,37.465 162.56,34.925 163.195,34.29 163.195,31.75 163.83,31.115 163.83,29.845 164.465,29.21 164.465,27.94 165.1,27.305 165.1,26.035 165.735,25.4 165.735,22.86 166.37,22.225 166.37,19.685 167.005,19.05 167.005,17.78 167.64,17.145 167.64,16.51 168.05,16.1 v1(169.77,16.1)
DIR3: P3.2 U1.5 | length 37.1
  Top Layer w0.2: 170.4,13.1 170.6,13.1 170.8,12.9 171.4,12.9 171.5,13 U1.5
  Top Layer w0.4: v1(167.875,13.1) 170.4,13.1
  Bottom Layer w0.4: P3.2 158.115,38.1 159.385,39.37 160.655,39.37 161.29,38.735 161.29,37.465 161.925,36.83 161.925,34.29 162.56,33.655 162.56,31.115 163.195,30.48 163.195,29.21 163.83,28.575 163.83,27.305 164.465,26.67 164.465,25.4 165.1,24.765 165.1,22.225 165.735,21.59 165.735,19.05 166.37,18.415 166.37,17.145 167.005,16.51 167.005,15.24 167.64,14.605 167.64,13.335 v1(167.875,13.1)
DIR4: P4.2 U1.6 | length 36.1
  Top Layer w0.2: 170.4,12.5 171.5,12.5 171.9,12.9 U1.6
  Top Layer w0.4: v1(167.205,12.5) 170.4,12.5
  Bottom Layer w0.4: P4.2 158.115,35.56 159.385,36.83 160.655,36.83 161.29,36.195 161.29,33.655 161.925,33.02 161.925,30.48 162.56,29.845 162.56,28.575 163.195,27.94 163.195,26.67 163.83,26.035 163.83,24.765 164.465,24.13 164.465,21.59 165.1,20.955 165.1,18.415 165.735,17.78 165.735,16.51 166.37,15.875 166.37,14.605 167.005,13.97 167.005,12.7 v1(167.205,12.5)
DIR5: P5.2 U2.15 | length 30.6
  Top Layer w0.2: 170.4,11 171.5,11 171.9,10.6 U2.15
  Top Layer w0.4: v1(166.575,11) 170.4,11
  Bottom Layer w0.4: P5.2 158.115,27.94 159.385,29.21 160.655,29.21 161.29,28.575 161.29,27.305 161.925,26.67 161.925,25.4 162.56,24.765 162.56,23.495 163.195,22.86 163.195,20.32 163.83,19.685 163.83,17.145 164.465,16.51 164.465,15.24 165.1,14.605 165.1,13.335 165.735,12.7 165.735,11.43 166.165,11 v1(166.575,11)
DIR6: P6.2 U2.16 | length 28.5
  Top Layer w0.2: 170.4,10.4 170.6,10.4 170.8,10.6 171.4,10.6 171.5,10.5 U2.16
  Top Layer w0.4: v1(167.082,10.4) 170.4,10.4
  Bottom Layer w0.4: P6.2 158.115,25.4 159.385,26.67 160.655,26.67 161.29,26.035 161.29,24.765 161.925,24.13 161.925,22.86 162.56,22.225 162.56,19.685 163.195,19.05 163.195,16.51 163.83,15.875 163.83,14.605 164.465,13.97 164.465,12.7 165.1,12.065 165.1,10.795 165.495,10.4 v1(167.082,10.4)
DIR7: P7.2 U2.5 | length 28
  Top Layer w0.2: 170.4,7.4 170.6,7.4 170.8,7.2 171.4,7.2 171.5,7.3 U2.5
  Top Layer w0.4: v1(167.225,7.4) 170.4,7.4
  Bottom Layer w0.4: P7.2 158.115,22.86 159.385,24.13 160.655,24.13 161.29,23.495 161.29,22.225 161.925,21.59 161.925,19.05 162.56,18.415 162.56,15.875 163.195,15.24 163.195,13.97 163.83,13.335 163.83,12.065 164.465,11.43 164.465,10.16 v1(167.225,7.4)
DIR8: P8.2 U2.6 | length 27
  Top Layer w0.2: 170.4,6.8 171.5,6.8 171.9,7.2 U2.6
  Top Layer w0.4: v1(166.555,6.8) 170.4,6.8
  Bottom Layer w0.4: P8.2 158.115,20.32 159.385,21.59 160.655,21.59 161.29,20.955 161.29,18.415 161.925,17.78 161.925,15.24 162.56,14.605 162.56,13.335 163.195,12.7 163.195,11.43 163.83,10.795 163.83,9.525 v1(166.555,6.8)
DIR9: P9.2 U3.15 | length 21.5
  Top Layer w0.2: 170.4,5.3 171.5,5.3 171.9,4.9 U3.15
  Top Layer w0.4: v1(165.515,5.3) 170.4,5.3
  Bottom Layer w0.4: P9.2 158.115,12.7 159.385,13.97 160.655,13.97 161.29,13.335 161.29,12.065 161.925,11.43 161.925,10.16 162.56,9.525 162.56,8.255 v1(165.515,5.3)
DIR10: P10.2 U3.16 | length 19.4
  Top Layer w0.2: 170.4,4.7 170.6,4.7 170.8,4.9 171.4,4.9 171.5,4.8 U3.16
  Top Layer w0.4: v1(164.845,4.7) 170.4,4.7
  Bottom Layer w0.4: P10.2 158.115,10.16 159.385,11.43 160.655,11.43 161.29,10.795 161.29,9.525 161.925,8.89 161.925,7.62 v1(164.845,4.7)
DIR11: P11.2 U3.5 | length 18.7
  Top Layer w0.2: 170.4,1.7 170.6,1.7 170.8,1.5 171.4,1.5 171.5,1.6 U3.5
  Top Layer w0.4: v1@166.624,1.7 170.4,1.7
  Bottom Layer w0.4: P11.2 158.115,7.62 159.385,8.89 160.655,8.89 161.29,8.255 161.29,6.985 v1(166.56,1.714)
DIR12: P12.2 U3.6 | length 17.8
  Top Layer w0.2: 170.4,1.1 171.5,1.1 171.9,1.5 U3.6
  Top Layer w0.4: v1(165.354,1.651) 165.905,1.1 170.4,1.1
  Bottom Layer w0.4: P12.2 158.115,5.08 159.385,6.35 160.655,6.35 v1(165.354,1.651)
GND: C12.2 C13.1 C14.2 C15.1 C16.2 C17.1 P1.1 P2.1 P3.1 P4.1 P5.1 P6.1 P7.1 P8.1 P9.1 P10.1 P11.1 P12.1 P13.1 P14.1 P15.1 P17.4 P20.15 P20.16 P21.15 P21.16 R1.1 R2.1 U1.8 U2.8 U3.8 | length 168.6
  Top Layer w0.2: U3.8 172.7,1.7 172.9,1.5 177.5,1.5 ; U2.8 172.7,7.4 172.9,7.2 177.1,7.2 ; U1.8 172.7,13.1 172.9,12.9 177.5,12.9 ; 175.1,1.5 C17.1 ; 175.1,7.2 C15.1 ; 175.1,12.9 C13.1 ; 176.3,1.5 C16.2 ; 176.3,7.2 C14.2 ; 176.3,12.9 C12.2
  Top Layer w0.4: v1(169.8,17.3) 169.39,17.3 168.91,17.78 168.91,31.076 R2.1
  Top Layer w0.8: R2.1@170.18,32.346 P17.4 ; 177.5,1.8 177.5,12.6 ; 177.5,3.81 P21.16
  Bottom Layer w0.4: v1(169.8,17.3) 170.9,17.3 171.2,17 171.2,1
  Bottom Layer w0.8: P15.1 154.94,2.794 ; P1.1 P2.1 P3.1 P4.1 P13.1 P5.1 P6.1 P7.1 P8.1 P14.1 P9.1 P10.1 P11.1 154.94,6.35 ; P21.15 184.15,1.27 183.515,0.635 165.1,0.635 162.179,3.556 159.258,3.556 158.496,2.794 154.94,2.794 ; 154.94,2.794 154.94,3.81 ; 154.94,3.81 P12.1 154.94,6.35 ; 154.94,3.81 P20.16 P20.15 154.94,6.35
GND_1: 
GND_2: C21.1 C22.1 C23.1 C24.1 C25.1 C26.1 C27.1 C28.1 C30.1 C31.1 E2.2 E2.3 FL2.1 FL2.3 P40.15 P40.16 P41.15 P41.16 P44.1 P44.2 P44.3 P44.4 P46.1 P56.1 P57.2 P58.2 R6.1 U5.A6 U5.B7 U5.C4 U5.D4 U5.E4 U5.F4 U5.F5 U5.G4 U5.G6 U5.G7 U5.H4 U5.H5 Y2.2 Y2.4 | length 115.3
  Top Layer w0.1: U5.C4 U5.A6
  Top Layer w0.11: 41.46,21.7 41.66,21.9 ; 43.46,21.3 43.66,21.5
  Top Layer w0.15: U5.G6 41.46,21.7 ; 41.66,21.9 U5.F5
  Top Layer w0.18: U5.B7 43.46,21.3 ; 43.66,21.5 U5.A6
  Top Layer w0.2: C23.1 40.56,20.8 ; 40.96,21.6 U5.H5 U5.H4 ; U5.F5 U5.F4 ; C30.1@42.56,19.7 42.56,20.8 ; U5.C4 U5.D4 U5.E4 U5.F4 ; U5.B7 43.36,21 43.16,20.8 42.56,20.8 ; U5.A6 44.06,21.6 45.96,19.7 C25.1 ; 40.56,20.8 40.56,21.6 ; 40.56,20.8 41.36,20.8 ; 40.56,21.6 40.56,22.2 40.76,22.4 U5.H4 ; 40.56,21.6 U5.G6 U5.G7 41.36,20.8 ; U5.H4 U5.G4 U5.F4 ; 41.36,20.8 42.56,20.8
  Top Layer w0.3: C27.1 47.76,23.8 ; C26.1 47.66,24.8 ; C31.1 47.76,25.8
  Top Layer w0.4: P46.1 22.86,29.21 22.225,29.845 22.225,34.925 22.86,35.56 24.765,35.56 25.4,36.195 25.4,42.545 26.035,43.18 29.845,43.18 ; 39.76,27.5 C24.1 Y2.2@41.81,26.9 ; 40.56,18.495 C23.1 ; 41.26,26.9 41.26,27.5 ; 42.76,18.495 C30.1 ; Y2.4 Y2.4@43.06,25.9 ; C21.1 Y2.4@43.06,25.9 ; v1(43.66,25.8) 43.16,25.8 Y2.4@43.06,25.9 ; 44.06,27.5 v1(44.06,26.8) C28.1 ; 45.96,18.495 C25.1
  Top Layer w0.5: 49.862,35.46 P58.2@51.42,35.46 ; 49.862,40.54 51.42,40.54 51.42,42.098 ; P58.2@56.5,35.46 58.057,35.46 ; 56.5,42.098 56.5,40.54 58.057,40.54
  Top Layer w0.8: 0.96,2.5 0.96,3 1.77,3.81 P40.16 ; 6.35,2.54 6.35,3.81 ; 11.049,5.461 R6.1 ; 11.43,2.54 11.43,3.81 ; P44.1 13.97,5.08 ; 15.24,2.54 15.24,3.81 ; P44.2 16.51,5.08 ; 19.46,2.5 19.46,3 18.65,3.81 P44.4 ; 24.13,2.54 P56.1 ; 37.846,14.224 P57.2 39.37,16.51 ; P40.16 P40.15 P41.15 8.89,5.08 ; P40.16 6.35,3.81 ; 6.35,3.81 P41.16 ; P41.16 8.89,5.08 ; P41.16 11.43,3.81 ; 8.89,5.08 13.97,5.08 ; 11.43,3.81 P44.3 ; P44.3 13.97,5.08 ; P44.3 15.24,3.81 ; 13.97,5.08 16.51,5.08 ; 15.24,3.81 P44.4 ; P44.4 16.51,5.08
  Bottom Layer w0.4: v1(43.66,25.8) 43.66,26.1 44.06,26.5 v1(44.06,26.8)
GND_3: P59.15 P59.16 P60.1 P60.12 | length 41.1
  Top Layer w0.8: P59.15 194.31,6.35 194.945,6.985 194.945,19.05 195.58,19.685 196.85,19.685 ; P60.1 196.85,19.685 ; P60.12 200.66,34.29 201.295,33.655 201.295,20.32 200.66,19.685 196.85,19.685
I2C_SCL_2: P43.2 U5.G2 | length 52.9
  Top Layer w0.4: v1(31.115,3.175) 33.655,5.715 v1(33.655,23.495)
  Bottom Layer w0.2: 34.925,23.495 35.56,23.495 36.865,24.8 39.66,24.8 41.26,23.2 v2(41.36,23.2)
  Bottom Layer w0.4: P43.2 16.51,10.795 18.415,8.89 18.415,4.445 21.59,1.27 29.21,1.27 v1(31.115,3.175) ; v1(33.655,23.495) 34.925,23.495
I2C_SDA_2: P43.4 U5.D2 | length 56.3
  Top Layer w0.4: v1(32.385,3.175) 34.29,5.08 v1(34.29,25.4)
  Bottom Layer w0.2: 34.925,25.4 35.86,25.4 36.46,26 39.16,26 39.26,26.1 40.16,26.1 40.66,25.6 40.66,25.4 41.56,24.5 41.96,24.5 42.56,23.9 v2(42.56,23.2)
  Bottom Layer w0.4: P43.4 17.145,8.89 17.78,8.255 17.78,3.81 20.955,0.635 29.845,0.635 v1(32.385,3.175) ; v1(34.29,25.4) 34.925,25.4
MLDO_IN_1: 
MLDO_IN_2: C31.2 P39.6 P39.8 U5.A3 | length 31.5
  Top Layer w0.2: U5.A3 44.036,22.8 44.76,23.524 44.76,25.2 v1(45.06,25.5)
  Top Layer w0.4: v1(45.06,25.5) 45.36,25.8 C31.2
  Bottom Layer w0.2: 37.465,27.94 39.37,27.94 ; 39.37,27.9 44.56,27.9 45.06,27.4 v1(45.06,25.5)
  Bottom Layer w0.8: P39.6 26.67,31.75 30.48,27.94 37.465,27.94
MLDO_OUT_1: 
MLDO_OUT_2: C23.2 P39.7 P48.1 U5.C6 | length 57.3
  Top Layer w0.4: C23.2 v1(41.56,20.1)
  Top Layer w0.8: P48.1 25.4,8.89 26.67,10.16 26.67,31.75 P39.7
  Bottom Layer w0.2: v1(41.56,20.1) 42.46,20.1 42.76,20.4 42.76,21.4 v2(42.96,21.6)
  Bottom Layer w0.4: P48.1 25.4,8.89 26.035,9.525 26.035,11.43 26.67,12.065 38.1,12.065 41.56,15.525 v1(41.56,20.1)
NetC9_1: 
NetC9_2: 
NetE1_1: 
NetE2_1: E2.1 W1.1 | length 1.6
  Top Layer w0.6: W1.1 E2.1
NetE3_1: E3.1 P61.1 | length 2.2
  Top Layer w0.5: 214.4,35.5 E3.1@214.4,37.75
NetE3_2: E3.2 E3.3 P61.2 | length 9.3
  Top Layer w0.5: 210.283,27.46 211.84,27.46 211.84,25.903 ; 210.283,32.54 P61.2@211.84,32.54 ; 216.92,25.903 216.92,27.46 218.478,27.46 ; P61.2@216.92,32.54 218.478,32.54
NetE4_1: E4.1 P62.1 | length 2.2
  Top Layer w0.5: E4.1 214.4,7.5
NetE4_2: E4.2 P62.2 | length 9.3
  Top Layer w0.5: 210.303,13.46 P62.2@211.86,13.46 ; 210.303,18.54 211.86,18.54 211.86,20.098 ; P62.2@216.94,13.46 218.498,13.46 ; 216.94,20.098 216.94,18.54 218.498,18.54
NetP16_2: P16.2 P17.2 R2.2 | length 12.7
  Top Layer w0.8: R2.2 174.498,32.258 175.26,33.02 P17.2
  Bottom Layer w0.8: P17.2 P16.2
NetP16_4: P16.4 P17.3 R1.2 | length 8.5
  Top Layer w0.8: R1.2 172.72,34.71 P17.3
  Bottom Layer w0.8: P17.3 P16.4
NetP18_2: P18.2 P19.1 | length 5.1
  Top Layer w0.8: P19.1 P18.2
NetP18_3: P18.3 P19.3 | length 5.1
  Top Layer w0.8: P19.3 P18.3
NetP27_3: 
NetP27_4: 
NetP45_3: P45.3 R5.2 | length 3.1
  Top Layer w0.8: R5.2 11.469,13.97 P45.3
NetP45_4: P45.4 R5.1 R6.2 | length 9.9
  Top Layer w0.5: R5.1@10.795,12.065 12.065,12.065 12.7,12.7 15.24,12.7 P45.4
  Top Layer w0.8: R6.2 R5.1
NetP57_1: P57.1 U5.G5 | length 6.1
  Bottom Layer w0.2: 37.815,21.355 38.26,21.8 41.16,21.8 v2(41.36,22)
  Bottom Layer w0.4: P57.1@37.815,19.055 37.815,21.355
NetP58_1: P58.1 W2.2 | length 6
  Top Layer w0.5: W2.2 53.96,29.5
O\E\1: P13.2 U1.7 | length 34
  Top Layer w0.2: 170.4,11.9 171.4,11.9 172.3,12.8 U1.7
  Top Layer w0.4: v1(166.535,11.9) 170.4,11.9
  Bottom Layer w0.4: P13.2 158.115,31.75 159.385,33.02 160.655,33.02 161.29,32.385 161.29,29.845 161.925,29.21 161.925,27.94 162.56,27.305 162.56,26.035 163.195,25.4 163.195,24.13 163.83,23.495 163.83,20.955 164.465,20.32 164.465,17.78 165.1,17.145 165.1,15.875 165.735,15.24 165.735,13.97 166.37,13.335 166.37,12.065 v1(166.535,11.9)
O\E\2: P14.2 U2.7 | length 24.9
  Top Layer w0.2: 170.4,6.2 171.4,6.2 172.3,7.1 U2.7
  Top Layer w0.4: v1(165.885,6.2) 170.4,6.2
  Bottom Layer w0.4: P14.2 158.115,16.51 159.385,17.78 160.655,17.78 161.29,17.145 161.29,14.605 161.925,13.97 161.925,12.7 162.56,12.065 162.56,10.795 163.195,10.16 163.195,8.89 v1(165.885,6.2)
O\E\3: P15.2 U3.7 | length 17.2
  Top Layer w0.2: 170.4,0.5 171.4,0.5 172.3,1.4 U3.7
  Top Layer w0.4: v1(163.3,0.5) 170.4,0.5
  Bottom Layer w0.4: P15.2 158.115,1.27 159.385,2.54 161.29,2.54 163.3,0.53 v1(163.3,0.5)
P23_1: 
P23_11: 
P40_1: P40.1 P41.1 P42.1 P42.3 | length 12.7
  Top Layer w0.8: P40.1 P41.1 P42.1 P42.3
P40_11: P40.11 P41.11 P45.1 | length 10.2
  Top Layer w0.8: P40.11 P41.11 P45.1
P40_13: P40.13 P41.13 P43.1 | length 10.2
  Bottom Layer w0.8: P40.13 P41.13 P43.1
P40_14: P40.14 P41.14 P43.3 | length 10.2
  Bottom Layer w0.8: P40.14 P41.14 P43.3
RF: C29.2 FL2.4 | length 2.4
  Top Layer w0.4: C29.2 FL2.4
RF_IO: C29.1 U5.A5 | length 1.6
  Top Layer w0.4: 43.86,22 C29.1
SLOW_CLK_1: 
SLOW_CLK_2: P45.2 U5.F6 | length 31.5
  Bottom Layer w0.2: 39.16,20.3 39.16,21 39.56,21.4 41.56,21.4 v2(41.76,21.6)
  Bottom Layer w0.4: P45.2 17.78,15.24 38.735,15.24 39.16,15.665 39.16,20.3
SLOW_CLK_3: P59.11 P60.3 | length 13.2
  Top Layer w0.8: P59.11 193.04,16.51 193.675,17.145 193.675,23.495 194.31,24.13 P60.3
SRAM_LDO_OUT_1: 
SRAM_LDO_OUT_2: C28.2 P49.1 U5.A1 | length 35.1
  Top Layer w0.2: v1(44.66,26) 44.96,26.3 45.36,26.3 C28.2
  Top Layer w0.4: P49.1 25.4,20.32 v1(25.4,27.94)
  Bottom Layer w0.2: 29.21,27.94 29.845,27.305 38.735,27.305 38.93,27.5 44.46,27.5 44.66,27.3 v1(44.66,26) 44.56,25.9 44.56,23.8 44.36,23.6 v2(43.76,23.6)
  Bottom Layer w0.4: v1(25.4,27.94) 29.21,27.94
TX_DBG_1: 
TX_DBG_2: P54.1 U5.H2 | length 24.7
  Top Layer w0.2: v1(34.925,20.32) 35.28,20.32 36.36,21.4 36.36,22 37.56,23.2 U5.H2
  Top Layer w0.4: v1(30.48,13.97) v1(30.48,20.32)
  Bottom Layer w0.4: P54.1 v1(30.48,13.97) ; v1(30.48,20.32) v1(34.925,20.32)
VBAT_1: 
VBAT_2: P39.1 P42.2 P42.4 | length 10.2
  Top Layer w0.8: P42.4 P42.2 P39.1
VBAT_3: P59.1 P60.2 | length 35.7
  Bottom Layer w0.8: P59.1 190.5,43.18 191.135,43.815 200.66,43.815 201.295,43.18 201.295,22.225 200.66,21.59 P60.2
VCCA: C12.1 C14.1 C16.1 P1.3 P2.3 P3.3 P4.3 P5.3 P6.3 P7.3 P8.3 P9.3 P10.3 P11.3 P12.3 P13.3 P14.3 P15.3 P16.1 P16.3 P17.1 P20.1 P21.1 U1.14 U2.14 U3.14 | length 223
  Top Layer w0.2: U3.14 172.3,5.5 ; v1(172.3,5.8) 172.3,5.5 ; U2.14 v1(172.3,11.5) ; 172.3,11.2 175.9,11.2 176.3,10.8 C14.1 ; U1.14 v1(172.3,17.2) ; 172.3,16.9 175.9,16.9 176.3,16.5 C12.1 ; C16.1 176.3,5.1 175.9,5.5 172.3,5.5
  Top Layer w0.4: P16.3 P16.3@172.72,45.085 ; P16.1@174.625,45.085 P16.1
  Top Layer w0.8: P20.1 149.86,44.45 150.495,45.085 172.72,45.085 174.625,45.085 183.515,45.085 184.15,44.45 P21.1 ; P15.3 P12.3
  Bottom Layer w0.4: P20.1 149.86,44.45 150.495,45.085 155.575,45.085 156.21,44.45 156.21,41.91 ; P12.3 159.385,5.08 158.115,3.81 156.845,3.81 156.21,4.445 156.21,6.35 ; P11.3 159.385,7.62 158.115,6.35 156.21,6.35 ; P10.3 159.385,10.16 158.115,8.89 156.21,8.89 ; P9.3 159.385,12.7 158.115,11.43 156.21,11.43 ; P14.3 159.385,16.51 158.115,15.24 156.21,15.24 ; P8.3 159.385,20.32 158.115,19.05 156.21,19.05 ; P7.3 159.385,22.86 158.115,21.59 156.21,21.59 ; P6.3 159.385,25.4 158.115,24.13 156.21,24.13 ; P5.3 159.385,27.94 158.115,26.67 156.21,26.67 ; P13.3 159.385,31.75 158.115,30.48 156.21,30.48 ; P4.3 159.385,35.56 158.115,34.29 156.21,34.29 ; P3.3 159.385,38.1 158.115,36.83 156.21,36.83 ; P2.3 159.385,40.64 158.115,39.37 156.21,39.37 ; P1.3 159.385,43.18 158.115,41.91 156.21,41.91 ; v1(172.3,5.8) 172.3,20.105 171.45,20.955 171.45,30.48 172.085,31.115 177.165,31.115 177.8,31.75 P17.1 ; 156.21,6.35 156.21,8.89 ; 156.21,8.89 156.21,11.43 ; 156.21,11.43 156.21,15.24 ; 156.21,15.24 156.21,19.05 ; 156.21,19.05 156.21,21.59 ; 156.21,21.59 156.21,24.13 ; 156.21,24.13 156.21,26.67 ; 156.21,26.67 156.21,30.48 ; 156.21,30.48 156.21,34.29 ; 156.21,34.29 156.21,36.83 ; 156.21,36.83 156.21,39.37 ; 156.21,39.37 156.21,41.91
  Bottom Layer w0.8: P16.1 176.53,44.45 177.8,43.18 P17.1
VCCB: C13.2 C15.2 C17.2 P19.2 P19.4 P20.2 P21.2 U1.13 U2.13 U3.13 | length 110.2
  Top Layer w0.2: U3.13 172.7,4.7 173,5 v1(175.7,5) ; U2.13 172.7,10.4 173,10.7 v1(175.7,10.7) ; U1.13 172.7,16.1 173,16.4 175.1,16.4 ; C17.2 175.1,5 ; C15.2 175.1,10.7 ; C13.2 175.1,16.4 ; v1(175.7,16.4) 175.1,16.4
  Top Layer w0.4: 153.035,39.37 161.925,39.37 161.925,41.275 161.29,41.91 153.67,41.91 153.035,41.275 153.035,39.37
  Top Layer w0.8: P20.2 153.035,39.37 ; 161.925,39.37 179.705,39.37 ; P19.4 P19.2 178.435,21.59 179.705,22.86 179.705,39.37 ; P21.2 179.705,39.37
  Bottom Layer w0.4: 173,10.7 v1(175.7,10.7) ; 173,16.4 v1(175.7,16.4) ; P19.4@173,21.6 173,5.5 173.5,5 v1(175.7,5)
VIO_1: 
VIO_2: P39.3 P39.5 P40.2 P41.2 P47.1 P55.1 U5.C2 | length 82.7
  Top Layer w0.8: P40.2 P41.2 11.43,39.37 13.97,36.83 P39.5 P39.3 ; 19.685,26.67 P47.1 ; 19.685,36.83 19.685,20.955 20.955,19.685 v3(20.955,11.43)
  Bottom Layer w0.2: 37.465,26.6 37.484,26.619 ; 37.465,26.67 40.09,26.67 41.06,25.7 41.06,25.5 41.76,24.8 42.16,24.8 42.96,24 v2(42.96,23.2)
  Bottom Layer w0.8: v3(20.955,11.43) 20.955,7.62 22.225,6.35 P55.1 ; P47.1 37.465,26.67
XTAL_M_1: 
XTAL_M_2: C22.2 U5.B2 Y2.3 | length 4.7
  Top Layer w0.4: C22.2 41.86,25.9 41.96,25.8 v1(41.96,25.3)
  Bottom Layer w0.254: v1(41.96,25.3) 42.26,25.3 43.36,24.2 v2(43.36,23.2)
XTAL_P_1: 
XTAL_P_2: C21.2 U5.A2 Y2.1 | length 4.3
  Top Layer w0.254: Y2.1@43.16,26.6 43.56,26.6 44.16,26 44.16,23.387 43.973,23.2 U5.A2
pads on no net: P18.1 P18.4 P59.2 P59.7 P59.8 P59.9 P59.10 P59.13 P59.14 P60.6 P60.8 P60.10 P60.11 P60.13 P60.15 P60.16 P60.17 P60.18 U5.C3 U5.C5 U5.C7 U5.D3 U5.D5 U5.D6 U5.D7 U5.E3 U5.E5 U5.E6 U5.E7 U5.F1 U5.F3 U5.F7 U5.H7

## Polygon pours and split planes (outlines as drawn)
NetE4_2 on Bottom Layer "Bottom Layer-No Net" (solid, pour order 9): 202.5,22.5 202.5,5 229.5,5 229.5,22.5
NetE3_2 on Bottom Layer "Bottom Layer-No Net" (solid, pour order 8): 202.5,23.5 202.5,38 229.5,38 229.5,23.5
GND_2 on Bottom Layer "Bottom Layer-No Net" (solid, pour order 7): 42.06,45.8 42.06,27 60.46,27 60.46,45.8
NetE4_2 on Top Layer "Bottom Layer-No Net" (solid, pour order 12): 202.5,22.5 229.5,22.5 229.5,5 202.5,5
NetE3_2 on Top Layer "Bottom Layer-No Net" (solid, pour order 11): 202.5,23.5 229.5,23.5 229.5,38 202.5,38
GND_2 on Top Layer "Bottom Layer-No Net" (solid, pour order 10): 47.76,45.7 60.46,45.7 60.46,22.5 47.76,22.5

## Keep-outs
Keep-Out Layer:
  lines w0.2: 146.05,0 146.05,45.72 ; 187.96,0 187.96,45.72 ; 201.93,0 201.93,45.72

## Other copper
Top Layer:
  rectangle net GND_2: 47.46,22.5 51.76,27.5
  rectangle net GND_2: 47.46,0 60.46,21.5
  rectangle net GND_2: 0.46,0 47.625,2.5
  region net GND_2: 47.86,27.4 39.46,27.4 38.1,26.035 34.29,26.035 33.02,24.765 31.115,24.765 30.48,24.13 30.48,22.86 29.21,21.59 28.575,21.59 28.575,32.385 29.21,33.02 29.21,38.1 27.96,39.4 27.96,45.7 47.86,45.7
  region net GND_2: 32.36,2.5 34.925,5.08 34.925,14.605 35.56,15.24 38.735,15.24 39.37,15.875 39.37,18.415 40.005,19.05 46.355,19.05 46.46,19.2 46.46,19.8 46.26,20 46.06,20 44.36,21.7 47.26,21.7 47.46,21.5 47.46,2.5
  region net NetE4_1: 213.4,16 215.4,16 215.4,6.9 214.6,5.9 214.2,5.9 213.4,6.9
  pour cut-out: 211,19.5 217.8,19.5 217.8,12.5 218.694,12.497 219.4,11.786 219.4,6.9 217.3,6.9 216.05,5.5 216.05,4.8 212.9,4.8 212.9,5.5 211.5,6.9 209.4,6.9 209.4,11.786 210.109,12.497 211,12.5
  pour cut-out: 211,26.7 217.8,26.6 217.8,33.5 218.7,33.5 219.4,34.2 219.4,36.1 217.3,36.1 216.05,37.5 216.05,38.2 213.6,38.2 211.5,36.1 209.4,36.1 209.4,34.2 210.1,33.5 211,33.5
  region net NetE3_1: 213.4,30 215.4,30 215.4,36.1 214.6,37.1 214.2,37.1 213.4,36.1
  region net NetE3_2: 211.5,36.1 212,36.1 213.722,37.835 213.7,38 210.135,38 210.135,37.665 210.4,37.4
  region net GND_2: 47.46,22.5 47.26,22.3 44.36,22.3 45.46,23.4 47.46,23.4
  pour cut-out: 50.56,41.5 57.36,41.5 57.36,34.5 58.254,34.497 58.96,33.786 58.96,28.9 57.01,28.9 55.61,27.5 55.61,22.5 52.31,22.5 52.31,27.5 50.91,28.9 48.96,28.9 48.96,33.786 49.669,34.497 50.56,34.5
  region net NetP58_1: 52.96,38 54.96,38 54.96,28.9 54.16,27.9 53.76,27.9 52.96,28.9
Bottom Layer:
  region net GND_2: 29.845,0 34.925,5.08 34.925,8.89 38.735,8.89 45.76,15.9 45.76,20.3 44.36,21.7 44.36,22.3 45.76,23.7 51.26,23.7 51.26,27.2 60.46,27.2 60.46,0
  region net GND_2: 27.96,45.8 27.96,41.3 29.21,40.005 29.21,32.385 31.115,30.48 37.465,30.48 38.1,29.845 38.735,29.845 39.37,29.21 45.085,29.21 46.355,27.94 46.355,24.765 45.72,24.13 45.72,22.86 51.66,22.9 51.66,28.8 47.96,28.8 47.96,45.8
  region net CL1.5_LDO_OUT_2: 36.906,29.388 37.465,29.312 37.44,29.108 36.906,29.032
  region net ADCPPA_LDO_OUT_2: 36.906,30.023 37.465,29.947 37.44,29.743 36.906,29.667
  region net VIO_2: 38.735,26.772 37.567,27.051 37.592,26.289 38.735,26.568
  region net MLDO_IN_2: 38.735,28.042 37.567,28.321 37.592,27.559 38.735,27.838
  region net CL1.5_LDO_IN_2: 43.36,18.5 43.56,19.9 43.96,19.9 44.16,18.5
  region net BT_SHUTD_2: 39.675,20.371 39.776,20.65 40.03,20.625 40.056,20.32
  region net SLOW_CLK_2: 38.964,20.32 39.065,21.006 39.268,20.98 39.345,20.32
  region net NetP57_1: 37.694,21.514 38.227,21.895 38.329,21.717 37.998,21.26
  region net BT_TX_2: 35.56,18.517 35.001,18.593 35.001,18.237 35.56,18.313
  region net BT_RTS_2: 35.56,19.152 35.001,19.228 35.001,18.872 35.56,18.948
  region net I2C_SCL_2: 35.56,23.597 35.001,23.673 35.001,23.317 35.56,23.393
  region net DIG_LDO_OUT_2: 35.56,24.232 35.001,24.308 35.001,23.952 35.56,24.028
  region net AUD_FSYNC_2: 35.56,24.867 35.001,24.943 35.001,24.587 35.56,24.663
  region net I2C_SDA_2: 35.56,25.502 35.001,25.578 35.001,25.222 35.56,25.298
  pour cut-out: 211.614,16 ccw(c214.4,16) 214.4,13.214 ccw(c214.4,16) 217.186,16 ccw(c214.4,16) 214.4,18.786 ccw(c214.4,16)
  pour cut-out: 211.614,30 cw(c214.4,30) 214.4,32.786 cw(c214.4,30) 217.186,30 cw(c214.4,30) 214.4,27.214 cw(c214.4,30)
  pour cut-out: 51.174,38 ccw(c53.96,38) 53.96,35.214 ccw(c53.96,38) 56.746,38 ccw(c53.96,38) 53.96,40.786 ccw(c53.96,38)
